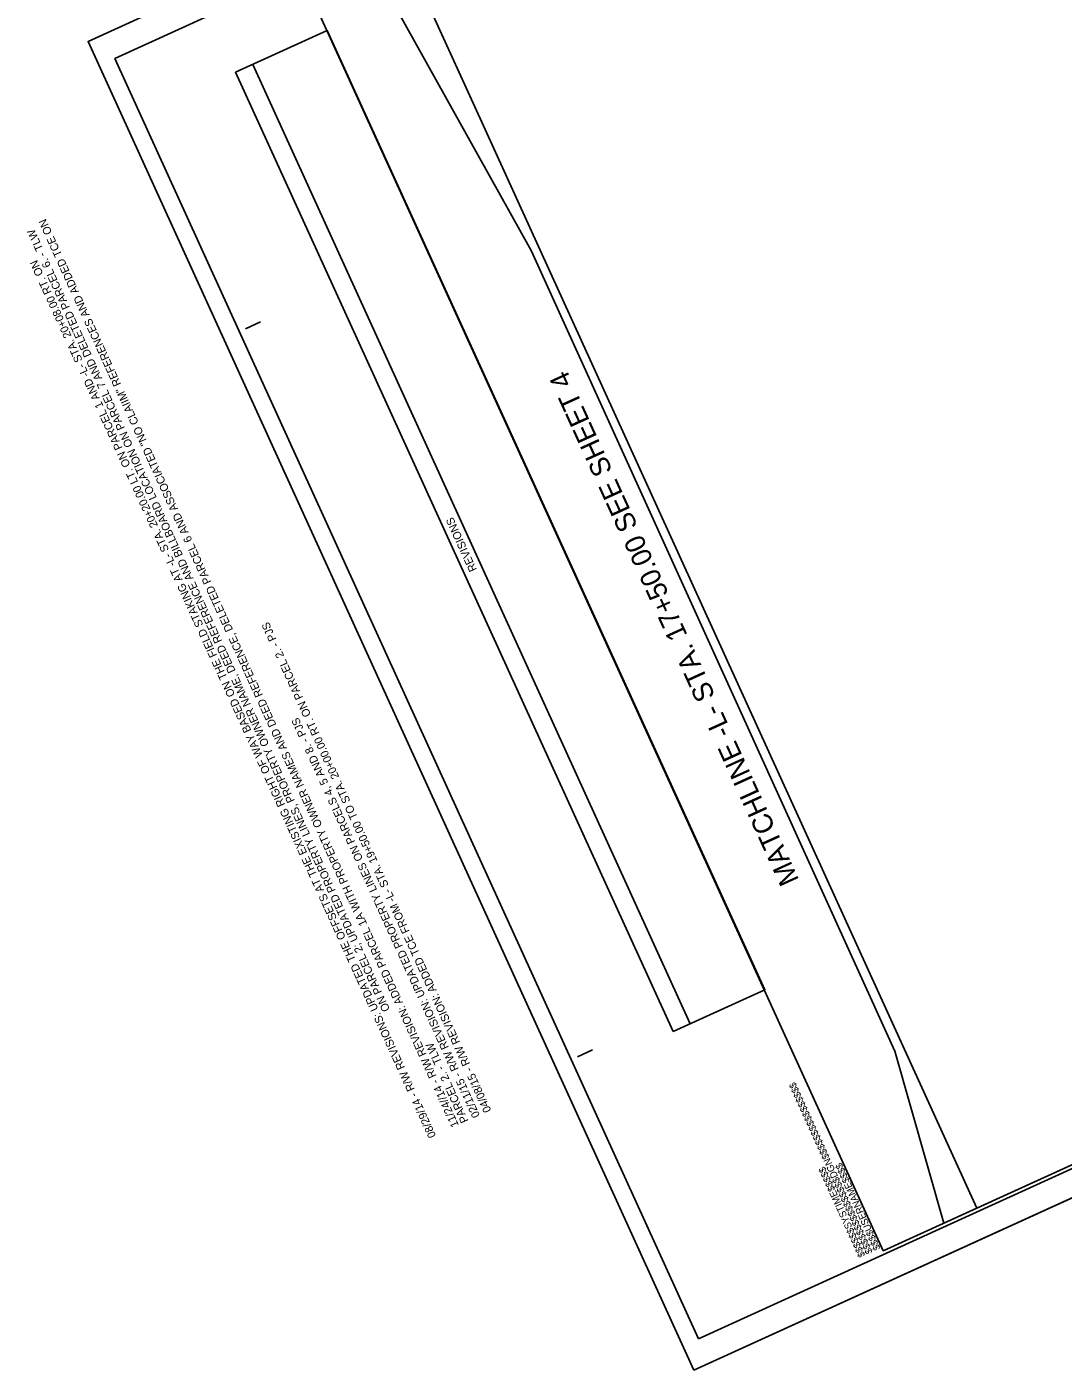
# Model space of a CAD drawing. Extents: x 2247864 to 2249896, y 662531 to 664296.
# Drawn here: x 2247864 to 2248641, y 662531 to 663539 of the extents above; entities that cross this region are included whole.
import ezdxf

# ---------------------------------------------------------------- set-up
doc = ezdxf.new("R2010")
doc.units = 0
for name, color, linetype in [('Matchline', 7, 'Continuous'), ('Matchline Text', 7, 'Continuous'), ('Prop Dimension Text', 7, 'Continuous'), ('Sheet Block Revision CELL', 7, 'Continuous'), ('Sheet Clip Boundary CELL', 7, 'Continuous'), ('Sheet Cutting Line CELL', 7, 'Continuous'), ('Sheet Layout Plan Border', 7, 'Continuous'), ('Sheet Plan CELL', 7, 'Continuous'), ('Sheet Plan Layout CELL', 7, 'Continuous'), ('Sheet Plot Border Inside CELL', 7, 'Continuous'), ('Sheet Plot Border Outside CELL', 7, 'Continuous')]:
    doc.layers.add(name, color=color, linetype=linetype)

msp = doc.modelspace()

# ---------------------------------------------------------------- linework, layer by layer
at = {"layer": 'Matchline'}
msp.add_line((2248241.7, 663371.1), (2248514.4, 662770.6), dxfattribs=at)
at = {"layer": 'Sheet Block Revision CELL'}
msp.add_line((2248360.8, 662791.1), (2248032.9, 663510.5), dxfattribs=at)
msp.add_lwpolyline([(2248348.2, 662785.3), (2248020.1, 663504.7), (2248088.7, 663536), (2248416.9, 662816.6)], close=True, dxfattribs=at)
at = {"layer": 'Sheet Clip Boundary CELL'}
msp.add_lwpolyline([(2248241.7, 663371.1), (2248514.4, 662770.6), (2248551.2, 662641.6), (2249564.6, 663103.3), (2249531.2, 663176.6), (2249788.9, 663294.1), (2249780.7, 663312.1), (2249743.4, 663294.9), (2249677.4, 663353.6), (2249425.3, 663908.7), (2249477.5, 663985.1), (2249305.3, 663906.7), (2249217.6, 664099.1), (2248115.8, 663597.1)], close=True, dxfattribs=at)
at = {"layer": 'Sheet Cutting Line CELL'}
for p, q in [((2249441.4, 664225.8), (2247909.5, 663527.8)), ((2247909.5, 663527.8), (2248363.6, 662531.3)), ((2248363.6, 662531.3), (2249895.5, 663229.4))]:
    msp.add_line(p, q, dxfattribs=at)
at = {"layer": 'Sheet Layout Plan Border'}
msp.add_lwpolyline([(2248198.1, 663481.5), (2248575.8, 662652.8), (2249849.7, 663233.3), (2249502.1, 663996.3), (2249329.8, 663917.8), (2249242.1, 664110.3), (2248140.4, 663608.2)], close=True, dxfattribs=at)
at = {"layer": 'Sheet Plan CELL'}
for p, q in [((2248027.5, 663312.3), (2248038.8, 663317.5)), ((2248276.3, 662766.3), (2248287.7, 662771.5)), ((2248505.7, 662620.9), (2248505.7, 662620.9))]:
    msp.add_line(p, q, dxfattribs=at)
for points in [[(2249435.3, 664198.3), (2248070.3, 663576.3), (2248505.7, 662620.9), (2249870.7, 663242.8)], [(2248505.7, 662620.9), (2248070.3, 663576.3), (2249253.3, 664115.4), (2249315.5, 663978.8), (2249497.5, 664061.8), (2249870.7, 663242.8)]]:
    msp.add_lwpolyline(points, close=True, dxfattribs=at)
at = {"layer": 'Sheet Plan Layout CELL'}
msp.add_lwpolyline([(2248070.3, 663576.3), (2248505.7, 662620.9), (2249870.7, 663242.8), (2249523, 664005.9), (2249305.3, 663906.7), (2249217.6, 664099.1)], close=True, dxfattribs=at)
at = {"layer": 'Sheet Plot Border Inside CELL'}
msp.add_lwpolyline([(2248367.1, 662554.9), (2249883.1, 663245.8), (2249445.6, 664205.8), (2247929.6, 663514.9)], close=True, dxfattribs=at)
at = {"layer": 'Sheet Plot Border Outside CELL'}
msp.add_lwpolyline([(2248363.6, 662531.3), (2249895.5, 663229.4), (2249441.4, 664225.8), (2247909.5, 663527.8)], close=True, dxfattribs=at)

# ---------------------------------------------------------------- texts
at = {"layer": 'Matchline Text'}
msp.add_text('MATCHLINE -L- STA. 17+50.00 SEE SHEET 4', height=15, rotation=114.4979, dxfattribs=at).set_placement((2248442.8, 662898.9))
at = {"layer": 'Prop Dimension Text'}
for s, p in [('11/24//14 - R/W REVISION: ADDED PARCEL 1A WITH PROPERTY OWNER NAMES AND DEED REFERENCE, DELETED PARCEL 6 AND ASSOCIATED "NO CLAIIM" REFERENCES AND ADDED TCE ON', (2248187.6, 662715)), ('  ON PARCEL 2; UPDATED PROPERTY LINES, PROPERTY OWNER NAME, DEED REFERENCE AND BILLBOARD LOCATION ON PARCEL 7 AND DELETED PARCEL 6. - TLW ', (2248137.8, 662797.7)), ('08/29/14 - R/W REVISIONS: UPDATED THE OFFSETS AT THE EXISTING RIGHT OF WAY BASED ON THE FIELD STAKING AT -L- STA. 20+20.00 LT. ON PARCEL 1 AND -L- STA. 20+08.00 RT. ON', (2248170.5, 662707.1)), ('04/08/15 - R/W REVISION: ADDED TCE FROM -L- STA. 19+50.00 TO STA. 20+00.00 RT. ON PARCEL 2. - PJS', (2248211.9, 662726.1)), ('02/11/15 - R/W REVISION: UPDATED PROPERTY LINES ON PARCELS 4, 5 AND 8. - PJS', (2248203.4, 662722.2)), ('PARCEL 2. - TLW', (2248194.8, 662718.3))]:
    msp.add_text(s, height=6, rotation=114.4979, dxfattribs=at).set_placement(p)
at = {"layer": 'Sheet Block Revision CELL'}
msp.add_text('REVISIONS', height=6, rotation=114.4979, dxfattribs=at).set_placement((2248201.1, 663131.7))
at = {"layer": 'Sheet Plan CELL'}
for s, p in [('$$$$$$$$$$$$$$$$DGN$$$$$$$$$$$$$$$$', (2248497.8, 662619.8)), ('$$$$USERNAME$$$$', (2248503.7, 662622.6)), ('$$$$$$SYSTIME$$$$$', (2248492.3, 662617.3))]:
    msp.add_text(s, height=5.25, rotation=114.4979, dxfattribs=at).set_placement(p)

doc.saveas('drawing.dxf')
